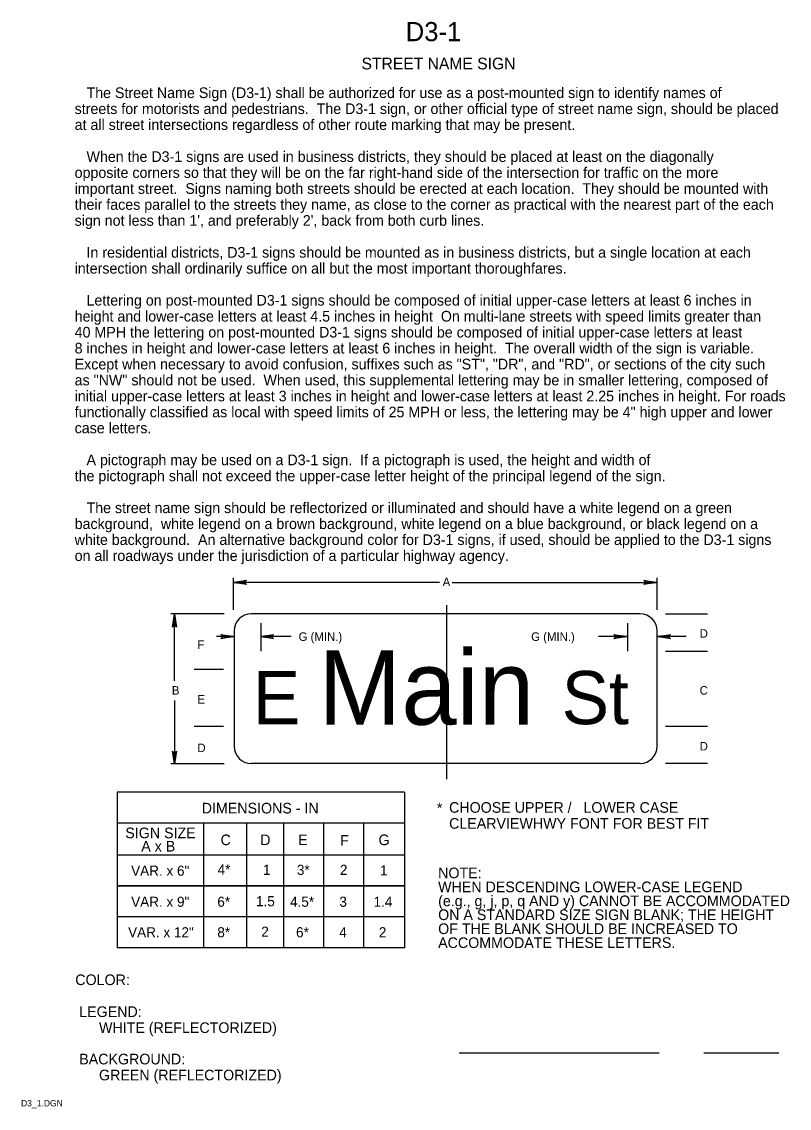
# Model space of a CAD drawing. Extents: x 0.013 to 0.193, y 0.004 to 0.259.
import ezdxf

# ---------------------------------------------------------------- set-up
doc = ezdxf.new("R2010")
doc.units = 0
doc.layers.add('1', color=7, linetype='Continuous')
doc.layers.add('3', color=7, linetype='Continuous')

# ---------------------------------------------------------------- blocks, each defined once
blk = doc.blocks.new('RARROW')
at = {"layer": '3'}
for p, q in [((-2.156, 0.285), (-2.2665, 0.384625)), ((-2.2665, 0.384625), (0, 0)), ((0, 0), (-2.2665, -0.379125)), ((-2.156, 0.285), (-2.075625, 0.12075)), ((0, 0), (-2.156, 0.285)), ((-2.14975, -0.2705), (0, 0)), ((-2.075625, 0.12075), (0, 0)), ((0, 0), (-2.074, -0.108)), ((-2.2665, -0.379125), (-2.14975, -0.2705)), ((-2.074, -0.108), (-2.14975, -0.2705))]:
    blk.add_line(p, q, dxfattribs=at)

msp = doc.modelspace()

# ---------------------------------------------------------------- linework, layer by layer
at = {"layer": '1'}
for p, q in [((0.11544, 0.01695), (0.16242, 0.01695)), ((0.17295, 0.01695), (0.19056, 0.01695))]:
    msp.add_line(p, q, dxfattribs=at)
at = {"layer": '3'}
for p, q in [((0.06245, 0.12107), (0.06245, 0.12857)), ((0.16194, 0.12107), (0.16194, 0.12857)), ((0.1108, 0.12749), (0.06244, 0.12749)), ((0.11379, 0.12749), (0.16194, 0.12749)), ((0.06023, 0.12007), (0.04769, 0.12007)), ((0.04856, 0.10436), (0.04856, 0.12007)), ((0.15794, 0.12011), (0.06656, 0.12011)), ((0.11244, 0.12211), (0.11244, 0.08124)), ((0.16394, 0.12011), (0.17381, 0.12011)), ((0.06886, 0.1179), (0.06886, 0.11132)), ((0.15498, 0.1179), (0.15498, 0.11132)), ((0.06256, 0.11611), (0.06256, 0.08899)), ((0.16194, 0.08899), (0.16194, 0.11611)), ((0.06244, 0.11474), (0.05844, 0.11474)), ((0.07595, 0.11474), (0.06883, 0.11474)), ((0.15498, 0.11474), (0.14815, 0.11474)), ((0.16881, 0.11474), (0.16194, 0.11474)), ((0.16394, 0.11136), (0.17381, 0.11136)), ((0.06006, 0.10699), (0.05319, 0.10699)), ((0.04856, 0.09974), (0.04856, 0.08486)), ((0.06006, 0.09361), (0.05319, 0.09361)), ((0.16394, 0.09374), (0.17381, 0.09374)), ((0.06023, 0.08487), (0.04769, 0.08487)), ((0.06656, 0.08499), (0.15794, 0.08499)), ((0.16394, 0.08499), (0.17381, 0.08499)), ((0.10257, 0.07821), (0.0351, 0.07821)), ((0.0351, 0.07821), (0.0351, 0.04162)), ((0.10257, 0.07821), (0.10257, 0.04162)), ((0.10257, 0.07091), (0.0351, 0.07091)), ((0.0554, 0.07076), (0.0554, 0.04162)), ((0.06551, 0.07091), (0.06551, 0.04162)), ((0.0742, 0.07076), (0.0742, 0.04162)), ((0.0836, 0.07076), (0.0836, 0.04162)), ((0.093, 0.07076), (0.093, 0.04162)), ((0.0351, 0.0635), (0.10257, 0.0635)), ((0.10257, 0.05621), (0.0351, 0.05621)), ((0.0351, 0.05621), (0.10257, 0.05621)), ((0.10257, 0.05621), (0.03534, 0.05621)), ((0.10257, 0.04892), (0.0351, 0.04892)), ((0.10257, 0.04892), (0.03534, 0.04892)), ((0.10257, 0.04162), (0.0351, 0.04162))]:
    msp.add_line(p, q, dxfattribs=at)
for centre, start, end in [((0.06657, 0.1161), 90, 180), ((0.15794, 0.1161), 0, 90), ((0.06657, 0.08897), 180, 270), ((0.15794, 0.08897), 270, 0)]:
    msp.add_arc(centre, 0.004, start, end, dxfattribs=at)

# ---------------------------------------------------------------- block references
at = {"layer": '3', "xscale": 0.0013236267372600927, "yscale": 0.001309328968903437}
for p, rotation in [((0.06244, 0.12749), 180), ((0.04856, 0.11999), 90), ((0.06883, 0.11474), 180), ((0.16206, 0.11474), 180), ((0.04856, 0.08486), -90)]:
    msp.add_blockref('RARROW', p, dxfattribs=dict(at, rotation=rotation))
for p in [(0.16181, 0.12749), (0.06244, 0.11474), (0.15481, 0.11474)]:
    msp.add_blockref('RARROW', p, dxfattribs=at)

# ---------------------------------------------------------------- texts
at = {"layer": '1'}
for s, height, p in [('D3-1', 0.0045, (0.10288, 0.25462)), ('STREET NAME SIGN', 0.0027503, (0.0925, 0.248)), ('COLOR:', 0.0025, (0.02525, 0.03288)), (' LEGEND:', 0.0025, (0.02525, 0.02538)), ('      WHITE (REFLECTORIZED)', 0.0024998, (0.02525, 0.02163)), (' BACKGROUND:', 0.0024998, (0.02525, 0.01425)), ('      GREEN (REFLECTORIZED)', 0.0024998, (0.02525, 0.0105)), ('D3_1.DGN', 0.0015, (0.0125, 0.00438))]:
    msp.add_text(s, height=height, dxfattribs=at).set_placement(p)
at = {"layer": '3'}
for s, height, p in [('   The Street Name Sign (D3-1) shall be authorized for use as a post-mounted sign to identify names of', 0.00249975, (0.0251, 0.24126)), ('streets for motorists and pedestrians.  The D3-1 sign, or other official type of street name sign, should be placed', 0.00249975, (0.0251, 0.23751)), ('at all street intersections regardless of other route marking that may be present.', 0.0024998, (0.0251, 0.23376)), ('   When the D3-1 signs are used in business districts, they should be placed at least on the diagonally', 0.00249975, (0.0251, 0.22626)), ('opposite corners so that they will be on the far right-hand side of the intersection for traffic on the more', 0.00249975, (0.0251, 0.22251)), ('important street.  Signs naming both streets should be erected at each location.  They should be mounted with', 0.00249975, (0.0251, 0.21876)), ('their faces parallel to the streets they name, as close to the corner as practical with the nearest part of the each', 0.00249975, (0.0251, 0.21501)), ("sign not less than 1', and preferably 2', back from both curb lines.", 0.0024998, (0.0251, 0.21126)), ('   In residential districts, D3-1 signs should be mounted as in business districts, but a single location at each', 0.00249975, (0.0251, 0.20376)), ('intersection shall ordinarily suffice on all but the most important thoroughfares.', 0.0024998, (0.0251, 0.20001)), ('   Lettering on post-mounted D3-1 signs should be composed of initial upper-case letters at least 6 inches in ', 0.00249975, (0.0251, 0.19251)), ('height and lower-case letters at least 4.5 inches in height  On multi-lane streets with speed limits greater than', 0.00249975, (0.0251, 0.18876)), ('40 MPH the lettering on post-mounted D3-1 signs should be composed of initial upper-case letters at least', 0.00249975, (0.0251, 0.18501)), ('8 inches in height and lower-case letters at least 6 inches in height.  The overall width of the sign is variable.  ', 0.00249975, (0.0251, 0.18126)), ('Except when necessary to avoid confusion, suffixes such as "ST", "DR", and "RD", or sections of the city such ', 0.00249975, (0.0251, 0.17751)), ('as "NW" should not be used.  When used, this supplemental lettering may be in smaller lettering, composed of', 0.00249975, (0.0251, 0.17376)), ('initial upper-case letters at least 3 inches in height and lower-case letters at least 2.25 inches in height. For roads ', 0.00249975, (0.0251, 0.17001)), ('functionally classified as local with speed limits of 25 MPH or less, the lettering may be 4" high upper and lower ', 0.00249975, (0.0251, 0.16626)), ('case letters.', 0.0024998, (0.0251, 0.16251)), ('   A pictograph may be used on a D3-1 sign.  If a pictograph is used, the height and width of ', 0.0024998, (0.0251, 0.15501)), ('the pictograph shall not exceed the upper-case letter height of the principal legend of the sign.', 0.0024998, (0.0251, 0.15126)), ('   The street name sign should be reflectorized or illuminated and should have a white legend on a green', 0.00249975, (0.0251, 0.14376)), ('background,  white legend on a brown background, white legend on a blue background, or black legend on a ', 0.00249975, (0.0251, 0.14001)), ('white background.  An alternative background color for D3-1 signs, if used, should be applied to the D3-1 signs ', 0.00249975, (0.0251, 0.13626)), ('on all roadways under the jurisdiction of a particular highway agency.', 0.0024998, (0.0251, 0.13251)), ('A', 0.002, (0.11156, 0.12661)), ('G (MIN.)', 0.002, (0.07771, 0.11374)), ('G (MIN.)', 0.002, (0.13235, 0.11374)), ('D', 0.002, (0.17194, 0.11449)), ('F', 0.002, (0.05394, 0.11186)), ('Main', 0.0175, (0.08235, 0.09405)), ('E', 0.0125, (0.06696, 0.09417)), ('St', 0.0125, (0.13951, 0.09417)), ('B', 0.002, (0.04794, 0.10111)), ('C', 0.002, (0.17194, 0.10111)), ('E', 0.002, (0.05394, 0.09899)), ('D', 0.002, (0.05394, 0.08761)), ('D', 0.002, (0.17194, 0.08799)), ('DIMENSIONS - IN', 0.0024998, (0.05495, 0.0732)), ('*', 0.0025, (0.1102, 0.07323)), ('CHOOSE UPPER /   LOWER CASE ', 0.0024998, (0.11307, 0.07336)), ('CLEARVIEWHWY FONT FOR BEST FIT', 0.0024998, (0.11307, 0.06961)), ('SIGN SIZE', 0.0025, (0.037, 0.06738)), ('A x B', 0.0025, (0.04075, 0.06425)), ('C', 0.0025, (0.05938, 0.06575)), ('D', 0.0025, (0.0687, 0.06575)), ('E', 0.0025, (0.07762, 0.06575)), ('F', 0.0025, (0.08747, 0.06563)), ('G', 0.0025, (0.0965, 0.06575)), ('VAR. x 6"', 0.002375, (0.03838, 0.05856)), ('4*', 0.002375, (0.05869, 0.05885)), ('1', 0.00238, (0.06933, 0.05878)), ('3*', 0.002375, (0.07731, 0.05876)), ('2', 0.00238, (0.08742, 0.05876)), ('1', 0.00238, (0.09686, 0.05866)), ('NOTE:', 0.0025, (0.1105, 0.05798)), ('WHEN DESCENDING LOWER-CASE LEGEND ', 0.0024998, (0.1105, 0.0547)), ('VAR. x 9"', 0.002375, (0.03838, 0.05127)), ('6*', 0.002375, (0.05862, 0.05127)), ('1.5', 0.002375, (0.06771, 0.0514)), ('4.5*', 0.002375, (0.07571, 0.05127)), ('3', 0.00238, (0.0873, 0.05127)), ('1.4', 0.002375, (0.09532, 0.05127)), ('(e.g., g, j, p, q AND y) CANNOT BE ACCOMMODATED ', 0.0024998, (0.1105, 0.05142)), ('ON A STANDARD SIZE SIGN BLANK; THE HEIGHT ', 0.0024998, (0.1105, 0.04815)), ('VAR. x 12"', 0.002375, (0.03766, 0.0441)), ('8*', 0.002375, (0.05862, 0.0441)), ('2', 0.00238, (0.06895, 0.04423)), ('6*', 0.002375, (0.07712, 0.0441)), ('4', 0.00238, (0.08726, 0.0441)), ('2', 0.00238, (0.09657, 0.0441)), ('OF THE BLANK SHOULD BE INCREASED TO ', 0.0024998, (0.1105, 0.04487)), ('ACCOMMODATE THESE LETTERS.', 0.0024998, (0.1105, 0.04159))]:
    msp.add_text(s, height=height, dxfattribs=at).set_placement(p)

doc.saveas('drawing.dxf')
